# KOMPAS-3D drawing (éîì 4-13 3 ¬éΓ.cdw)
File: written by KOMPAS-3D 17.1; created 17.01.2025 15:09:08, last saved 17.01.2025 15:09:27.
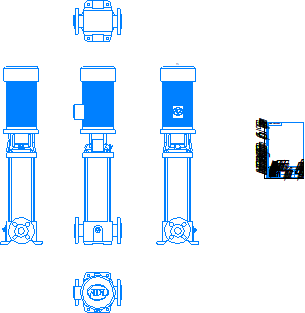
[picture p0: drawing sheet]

Sheet 1: A4, portrait

Title block, sheet 1: name: ВМН 4-13 3 кВт; designation: ВМН 4-13 3 кВт; sheets: 1; sheet format: A4; stored path: \\adlc.lan\data\АДЛ_ПКД\3D-модели\ADL production\Насосы ГРАНПАМП\Насосы ВМН\ВМН4\KOMPAS 2D\ВМН 4-13 3 кВт.cdw

Views: Вид 1, Спереди, Проекционный вид 2, Проекционный вид 3, Проекционный вид 4, Проекционный вид 5
Referenced files in \\adlc.lan\data\АДЛ_ПКД\3D-модели\ADL production\Насосы ГРАНПАМП\Насосы ВМН\ВМН4\KOMPAS 3D\: ВМН 4-13 3 кВт.m3d
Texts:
  Andrey
  АДЛ
Dimensions and other numbers on the sheet: 1:1; 1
